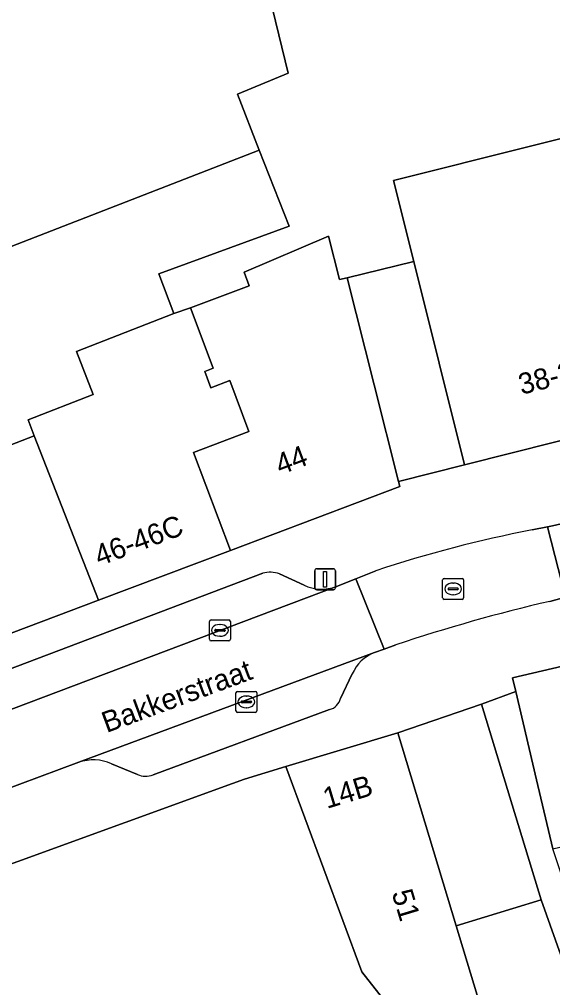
# Model space of a CAD drawing. Extents: x 160856 to 161310, y 384024 to 384878.
# Drawn here: x 160944.56 to 160970.01, y 384674.04 to 384720.28 of the extents above; entities that cross this region are included whole.
import ezdxf

# ---------------------------------------------------------------- set-up
doc = ezdxf.new("R2010")
doc.units = 0
for name, color, linetype in [('IMGEO_Erf', 7, 'Continuous'), ('IMGEO_Kolk', 7, 'Continuous'), ('IMGEO_Lichtmast', 7, 'Continuous'), ('IMGEO_Openbare_ruimte_label', 7, 'Continuous'), ('IMGEO_Pand', 7, 'Continuous'), ('IMGEO_Pand_nummerreeks', 7, 'Continuous'), ('IMGEO_Pand_overbouw', 7, 'Continuous'), ('IMGEO_Parkeervlak_open', 7, 'Continuous'), ('IMGEO_Rijbaan_lokaal_open', 7, 'Continuous'), ('IMGEO_Rioolput', 7, 'Continuous'), ('IMGEO_Voetpad_open', 7, 'Continuous')]:
    doc.layers.add(name, color=color, linetype=linetype)

msp = doc.modelspace()

# ---------------------------------------------------------------- linework, layer by layer
at = {"layer": 'IMGEO_Erf'}
msp.add_lwpolyline([(160954.094, 384731.251), (160957.385, 384717.71), (160954.963, 384716.711), (160956.01, 384714.035), (160957.429, 384710.406), (160951.212, 384708.132), (160951.927, 384706.229), (160952.723, 384706.502), (160955.527, 384707.559), (160955.281, 384708.212), (160959.313, 384709.933), (160959.838, 384707.852), (160960.205, 384707.945), (160963.386, 384708.712), (160962.416, 384712.593), (160975.435, 384715.845), (160974.846, 384718.23), (160973.834, 384722.103)], dxfattribs=at)
msp.add_lwpolyline([(161012.363, 384660.051), (160975.017, 384662.612), (160969.466, 384678.232), (160965.408, 384676.997), (160967.25, 384670.899), (160964.692, 384669.97), (160955.52, 384666.637), (160955.594, 384666.434), (160956.022, 384665.257), (160967.658, 384669.485), (160970.725, 384659.329), (160971.358, 384659.52), (160971.859, 384657.86), (160972.179, 384656.802), (160972.563, 384656.918), (160973.559, 384653.621), (160973.59, 384653.518), (161000, 384651.318), (161011.607, 384650.352), (161012.121, 384657.087)], close=True, dxfattribs=at)
at = {"layer": 'IMGEO_Kolk'}
for p, q in [((160953.632, 384690.678), (160953.632, 384691.53)), ((160953.707, 384691.604), (160954.559, 384691.604)), ((160954.12, 384691.384), (160954.145, 384691.384)), ((160954.633, 384691.53), (160954.633, 384690.678)), ((160953.891, 384691.098), (160953.891, 384691.11)), ((160954.329, 384691.061), (160953.931, 384691.061)), ((160953.934, 384691.147), (160954.332, 384691.147)), ((160954.143, 384690.824), (160954.118, 384690.824)), ((160954.375, 384691.11), (160954.375, 384691.098)), ((160954.559, 384690.604), (160953.707, 384690.604)), ((160954.893, 384687.261), (160954.893, 384688.113)), ((160954.968, 384688.187), (160955.82, 384688.187)), ((160955.381, 384687.967), (160955.406, 384687.967)), ((160955.894, 384688.113), (160955.894, 384687.261)), ((160955.152, 384687.681), (160955.152, 384687.693)), ((160955.59, 384687.644), (160955.192, 384687.644)), ((160955.195, 384687.73), (160955.593, 384687.73)), ((160955.636, 384687.693), (160955.636, 384687.681)), ((160955.82, 384687.187), (160954.968, 384687.187)), ((160955.404, 384687.407), (160955.379, 384687.407))]:
    msp.add_line(p, q, dxfattribs=at)
for points in [[(160953.632, 384690.678), (160953.632, 384691.53)], [(160953.707, 384691.604), (160954.559, 384691.604)], [(160954.633, 384691.53), (160954.633, 384690.678)], [(160954.559, 384690.604), (160953.707, 384690.604)], [(160954.893, 384687.261), (160954.893, 384688.113)], [(160954.968, 384688.187), (160955.82, 384688.187)], [(160955.894, 384688.113), (160955.894, 384687.261)], [(160955.82, 384687.187), (160954.968, 384687.187)]]:
    msp.add_lwpolyline(points, dxfattribs=at)
for centre, radius, start, end in [((160953.709, 384691.528), 0.0765, 91.552, 178.448), ((160953.709, 384691.528), 0.0765, 91.552, 178.448), ((160954.557, 384691.528), 0.0765, 1.552, 88.448), ((160954.557, 384691.528), 0.0765, 1.552, 88.448), ((160953.931, 384691.107), 0.0403, 85.8775, 175.7526), ((160953.928, 384691.097), 0.0366, 178.938, 274.7102), ((160954.332, 384691.104), 0.043, 264.8664, 352.4533), ((160954.336, 384691.109), 0.0386, 1.7309, 96.639), ((160953.709, 384690.68), 0.0765, 181.552, 268.448), ((160953.709, 384690.68), 0.0765, 181.552, 268.448), ((160954.557, 384690.68), 0.0765, 271.552, 358.448), ((160954.557, 384690.68), 0.0765, 271.552, 358.448), ((160954.97, 384688.111), 0.0765, 91.552, 178.448), ((160954.97, 384688.111), 0.0765, 91.552, 178.448), ((160955.818, 384688.111), 0.0765, 1.552, 88.448), ((160955.818, 384688.111), 0.0765, 1.552, 88.448), ((160955.192, 384687.69), 0.0403, 85.8775, 175.7526), ((160955.189, 384687.68), 0.0366, 178.938, 274.7102), ((160955.593, 384687.687), 0.043, 264.8664, 352.4533), ((160955.597, 384687.692), 0.0386, 1.7309, 96.639), ((160954.97, 384687.263), 0.0765, 181.552, 268.448), ((160954.97, 384687.263), 0.0765, 181.552, 268.448), ((160955.818, 384687.263), 0.0765, 271.552, 358.448), ((160955.818, 384687.263), 0.0765, 271.552, 358.448)]:
    msp.add_arc(centre, radius, start, end, dxfattribs=at)
for centre, major_axis, ratio, start_param, end_param in [((160954.119, 384691.104), (-0.387, 0.002), 0.722429, 4.712389, 7.853982), ((160954.144, 384691.104), (-0.39, 0.002), 0.717154, 1.570796, 4.712389), ((160955.38, 384687.687), (-0.387, 0.002), 0.722429, 4.712389, 7.853982), ((160955.405, 384687.687), (-0.39, 0.002), 0.717154, 1.570796, 4.712389)]:
    msp.add_ellipse(centre, major_axis=major_axis, ratio=ratio, start_param=start_param, end_param=end_param, dxfattribs=at)
at = {"layer": 'IMGEO_Lichtmast'}
for p, q in [((160958.655, 384693.142), (160958.655, 384693.942)), ((160958.655, 384693.942), (160958.655, 384693.142)), ((160958.755, 384694.042), (160959.545, 384694.042)), ((160959.545, 384694.042), (160958.755, 384694.042)), ((160959.645, 384693.942), (160959.645, 384693.142)), ((160959.645, 384693.142), (160959.645, 384693.942)), ((160959.545, 384693.042), (160958.755, 384693.042)), ((160958.755, 384693.042), (160959.545, 384693.042))]:
    msp.add_line(p, q, dxfattribs=at)
msp.add_lwpolyline([(160959.075, 384693.917), (160959.225, 384693.917), (160959.225, 384693.167), (160959.075, 384693.167), (160959.075, 384693.917)], dxfattribs=at)
for centre, start, end in [((160958.755, 384693.942), 90, 180), ((160958.755, 384693.942), 90, 180), ((160959.545, 384693.942), 0, 90), ((160959.545, 384693.942), 360, 90), ((160958.755, 384693.142), 180, 270), ((160958.755, 384693.142), 180, 270), ((160959.545, 384693.142), 270, 0), ((160959.545, 384693.142), 270, 0)]:
    msp.add_arc(centre, 0.1, start, end, dxfattribs=at)
at = {"layer": 'IMGEO_Pand'}
for points in [[(160956.01, 384714.035), (160954.963, 384716.711), (160957.385, 384717.71), (160954.094, 384731.251), (160953.852, 384731.189), (160953.769, 384731.511), (160913.229, 384715.759), (160919.422, 384699.819)], [(160975.435, 384715.845), (160962.416, 384712.593), (160963.386, 384708.712), (160965.811, 384699.01), (160972.317, 384700.651), (160976.168, 384701.622), (160976.207, 384701.405), (160978.898, 384701.99), (160978.712, 384702.734)], [(160947.286, 384704.414), (160951.927, 384706.229), (160951.212, 384708.132), (160957.429, 384710.406), (160956.01, 384714.035), (160919.422, 384699.819), (160919.502, 384699.614), (160923.413, 384689.547), (160933.596, 384693.502), (160932.991, 384695.058), (160935.994, 384696.225), (160935.806, 384696.709), (160940.055, 384698.364), (160945.27, 384700.396), (160944.973, 384701.159), (160948.085, 384702.371)], [(160961.498, 384702.822), (160960.205, 384707.945), (160959.838, 384707.852), (160959.313, 384709.933), (160955.281, 384708.212), (160955.527, 384707.559), (160952.723, 384706.502), (160953.809, 384703.62), (160953.411, 384703.47), (160953.705, 384702.691), (160954.6, 384703.029), (160955.518, 384700.595), (160952.864, 384699.594), (160954.629, 384694.918), (160962.721, 384697.973), (160962.66, 384698.215)], [(160952.723, 384706.502), (160951.927, 384706.229), (160947.286, 384704.414), (160948.085, 384702.371), (160944.973, 384701.159), (160945.27, 384700.396), (160948.331, 384692.54), (160954.629, 384694.918), (160952.864, 384699.594), (160955.518, 384700.595), (160954.6, 384703.029), (160953.705, 384702.691), (160953.411, 384703.47), (160953.809, 384703.62)], [(160945.27, 384700.396), (160940.055, 384698.364), (160935.806, 384696.709), (160935.994, 384696.225), (160932.991, 384695.058), (160933.596, 384693.502), (160923.413, 384689.547), (160925.586, 384683.954), (160948.331, 384692.54)], [(160976.93, 384682.175), (160974.983, 384690.451), (160968.1, 384688.831), (160968.254, 384688.176), (160969.245, 384683.965), (160970.021, 384680.67), (160974.604, 384681.749), (160975.573, 384677.634), (160975.957, 384677.724), (160977.607, 384670.712), (160980.024, 384671.281), (160980.215, 384671.326), (160980.72, 384671.445), (160980.648, 384671.734), (160979.186, 384677.568), (160979.023, 384677.53), (160978.741, 384678.728), (160977.718, 384678.488)], [(160964.692, 384669.97), (160967.25, 384670.899), (160965.408, 384676.997), (160962.626, 384686.212), (160957.27, 384684.595), (160960.908, 384674.794)], [(160955.594, 384666.434), (160955.52, 384666.637), (160964.692, 384669.97), (160960.908, 384674.794), (160957.27, 384684.595), (160955.307, 384684.002), (160954.733, 384683.794), (160929.276, 384674.544), (160933.47, 384663.572), (160941.279, 384666.602), (160945.923, 384666.697), (160951.642, 384666.521)]]:
    msp.add_lwpolyline(points, close=True, dxfattribs=at)
at = {"layer": 'IMGEO_Pand_overbouw'}
for points in [[(160965.811, 384699.01), (160963.386, 384708.712), (160960.205, 384707.945), (160961.498, 384702.822), (160962.66, 384698.215)], [(160965.408, 384676.997), (160969.466, 384678.232), (160968.085, 384682.767), (160966.621, 384687.573), (160962.626, 384686.212)]]:
    msp.add_lwpolyline(points, close=True, dxfattribs=at)
at = {"layer": 'IMGEO_Parkeervlak_open'}
for points in [[(160970.01, 384696.102), (160984.769, 384699.502)], [(160956.181, 384693.829), (160933.675, 384685.307), (160930.887, 384684.184)], [(160958.149, 384693.264), (160956.97, 384693.801)], [(160928.722, 384681.501), (160959.689, 384693.195)], [(160961.512, 384690.047), (160947.406, 384684.802)], [(160959.892, 384687.854), (160960.449, 384689.023)], [(160950.948, 384684.202), (160959.364, 384687.32)], [(160948.951, 384684.735), (160950.196, 384684.217)]]:
    msp.add_lwpolyline(points, dxfattribs=at)
for centre, radius, start, end in [((160956.534, 384692.65), 1.23, 69.253, 106.6821), ((160959, 384695.046), 1.974, 244.4573, 290.4119), ((160962.224, 384688.245), 1.938, 111.5427, 156.3162), ((160959.176, 384688.034), 0.739, 284.7767, 345.8707), ((160948.093, 384682.805), 2.112, 66.0394, 108.9944), ((160950.591, 384685.163), 1.025, 247.3262, 290.3884)]:
    msp.add_arc(centre, radius, start, end, dxfattribs=at)
at = {"layer": 'IMGEO_Rijbaan_lokaal_open'}
for points in [[(160963.386, 384708.712), (160960.205, 384707.945), (160961.498, 384702.822), (160962.66, 384698.215), (160965.811, 384699.01)], [(160947.406, 384684.802), (160961.512, 384690.047), (160961.975, 384690.212), (160960.623, 384693.571), (160959.689, 384693.195), (160928.722, 384681.501), (160927.644, 384681.106), (160928.902, 384677.875), (160929.794, 384678.201), (160943.625, 384683.404)], [(160962.626, 384686.212), (160965.408, 384676.997), (160969.466, 384678.232), (160968.085, 384682.767), (160966.621, 384687.573)]]:
    msp.add_lwpolyline(points, close=True, dxfattribs=at)
for points in [[(160988.789, 384701.138), (160987.198, 384700.153), (160984.769, 384699.502), (160970.01, 384696.102), (160969.772, 384696.053), (160970.624, 384692.689), (160970.861, 384692.752), (160971.03, 384692.792), (160993.576, 384698.147)], [(160969.878, 384692.489), (160970.624, 384692.689), (160969.772, 384696.053), (160969.031, 384695.9)], [(160961.573, 384693.953), (160960.623, 384693.571), (160961.975, 384690.212), (160962.526, 384690.408)]]:
    msp.add_lwpolyline(points, dxfattribs=at)
for centre, radius, start, end in [((160980.724, 384635.853), 61.175, 101.01919, 108.2432), ((160987.298, 384616.919), 77.551, 102.98057, 108.62799)]:
    msp.add_arc(centre, radius, start, end, dxfattribs=at)
at = {"layer": 'IMGEO_Rioolput'}
for p, q in [((160964.762, 384692.658), (160964.762, 384693.51)), ((160964.837, 384693.584), (160965.689, 384693.584)), ((160965.763, 384693.51), (160965.763, 384692.658)), ((160965.021, 384693.078), (160965.021, 384693.09)), ((160965.459, 384693.041), (160965.061, 384693.041)), ((160965.064, 384693.127), (160965.462, 384693.127)), ((160965.25, 384693.364), (160965.275, 384693.364)), ((160965.505, 384693.09), (160965.505, 384693.078)), ((160965.689, 384692.584), (160964.837, 384692.584)), ((160965.273, 384692.804), (160965.248, 384692.804))]:
    msp.add_line(p, q, dxfattribs=at)
for points in [[(160964.762, 384692.658), (160964.762, 384693.51)], [(160964.837, 384693.584), (160965.689, 384693.584)], [(160965.763, 384693.51), (160965.763, 384692.658)], [(160965.689, 384692.584), (160964.837, 384692.584)]]:
    msp.add_lwpolyline(points, dxfattribs=at)
for centre, radius, start, end in [((160964.839, 384693.508), 0.0765, 91.552, 178.448), ((160964.839, 384693.508), 0.0765, 91.552, 178.448), ((160965.687, 384693.508), 0.0765, 1.552, 88.448), ((160965.687, 384693.508), 0.0765, 1.552, 88.448), ((160965.061, 384693.087), 0.0403, 85.8775, 175.7526), ((160965.058, 384693.077), 0.0366, 178.938, 274.7102), ((160965.462, 384693.084), 0.043, 264.8664, 352.4533), ((160965.466, 384693.089), 0.0386, 1.7309, 96.639), ((160964.839, 384692.66), 0.0765, 181.552, 268.448), ((160964.839, 384692.66), 0.0765, 181.552, 268.448), ((160965.687, 384692.66), 0.0765, 271.552, 358.448), ((160965.687, 384692.66), 0.0765, 271.552, 358.448)]:
    msp.add_arc(centre, radius, start, end, dxfattribs=at)
for centre, major_axis, ratio, start_param, end_param in [((160965.249, 384693.084), (-0.387, 0.002), 0.722429, 4.712389, 7.853982), ((160965.274, 384693.084), (-0.39, 0.002), 0.717154, 1.570796, 4.712389)]:
    msp.add_ellipse(centre, major_axis=major_axis, ratio=ratio, start_param=start_param, end_param=end_param, dxfattribs=at)
at = {"layer": 'IMGEO_Voetpad_open'}
for points in [[(160994.23, 384705.618), (160995.811, 384707.21), (160999.036, 384711.374), (161000, 384712.619), (161001.824, 384714.974), (160998.487, 384714.721), (160996.631, 384712.258), (160990.485, 384704.401), (160980.053, 384702.083), (160979.817, 384703.005), (160978.712, 384702.734), (160978.898, 384701.99), (160976.207, 384701.405), (160976.168, 384701.622), (160972.317, 384700.651), (160965.811, 384699.01), (160962.66, 384698.215), (160962.721, 384697.973), (160954.629, 384694.918), (160948.331, 384692.54), (160925.586, 384683.954), (160926.724, 384680.788), (160927.644, 384681.106), (160928.722, 384681.501)], [(160969.031, 384695.9), (160969.772, 384696.053), (160970.01, 384696.102)], [(160959.689, 384693.195), (160960.623, 384693.571), (160961.573, 384693.953)], [(160930.887, 384684.184), (160933.675, 384685.307), (160956.181, 384693.829)], [(160956.97, 384693.801), (160958.149, 384693.264)], [(160971.03, 384692.792), (160970.861, 384692.752), (160970.624, 384692.689), (160969.878, 384692.489)], [(160929.794, 384678.201), (160928.902, 384677.875), (160928.003, 384677.547), (160928.927, 384675.368), (160929.276, 384674.544), (160954.733, 384683.794), (160955.307, 384684.002), (160957.27, 384684.595), (160962.626, 384686.212), (160966.621, 384687.573), (160968.254, 384688.176), (160968.1, 384688.831), (160974.983, 384690.451), (160981.722, 384692.037)], [(160962.526, 384690.408), (160961.975, 384690.212), (160961.512, 384690.047)], [(160960.449, 384689.023), (160959.892, 384687.854)], [(160975.646, 384663.885), (160970.021, 384680.67), (160969.245, 384683.965), (160968.254, 384688.176), (160966.621, 384687.573), (160968.085, 384682.767), (160969.466, 384678.232), (160975.017, 384662.612)], [(160959.364, 384687.32), (160950.948, 384684.202)], [(160947.406, 384684.802), (160943.625, 384683.404)], [(160950.196, 384684.217), (160948.951, 384684.735)]]:
    msp.add_lwpolyline(points, dxfattribs=at)
for centre, radius, start, end in [((160980.724, 384635.853), 61.175, 101.01919, 108.2432), ((160956.534, 384692.65), 1.23, 69.253, 106.6821), ((160959, 384695.046), 1.974, 244.4573, 290.4119), ((160987.298, 384616.919), 77.551, 102.98057, 108.62799), ((160962.224, 384688.245), 1.938, 111.5427, 156.3162), ((160959.176, 384688.034), 0.739, 284.7767, 345.8707), ((160948.093, 384682.805), 2.112, 66.0394, 108.9944), ((160950.591, 384685.163), 1.025, 247.3262, 290.3884)]:
    msp.add_arc(centre, radius, start, end, dxfattribs=at)

# ---------------------------------------------------------------- texts
at = {"layer": 'IMGEO_Openbare_ruimte_label'}
msp.add_text('Bakkerstraat', height=1, rotation=20.3012, dxfattribs=at).set_placement((160948.722, 384686.198))
at = {"layer": 'IMGEO_Pand_nummerreeks'}
for s, rotation, p in [('38-38A', 14.404, (160968.525, 384702.347)), ('44', 20.6838, (160957.012, 384698.512)), ('46-46C', 20.6838, (160948.375, 384694.16)), ('14B', 16.7993, (160959.235, 384682.577)), ('51', 286.799, (160962.322, 384678.569))]:
    msp.add_text(s, height=1, rotation=rotation, dxfattribs=at).set_placement(p)

doc.saveas('drawing.dxf')
